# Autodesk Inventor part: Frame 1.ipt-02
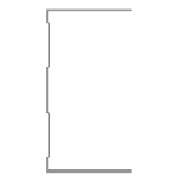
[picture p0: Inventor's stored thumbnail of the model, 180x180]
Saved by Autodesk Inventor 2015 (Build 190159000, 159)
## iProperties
IsCustomPart: 1
Created: 2015-04
Part Number: Frame 1.ipt-02
Material: Aluminum 6061
Description: Kévin Novo
Document SubType Name: Modeling
Standard: Kevin
Designer: suporte
Standards Organization: Kevin
Language: en-US
Size Designation: (Unnamed 2)
Categories: <MemberInstance><Categories><Category DisplayName="Structural Shapes" InternalName="089c4875-fa83-4c05-b084-43b9cc11f5ed" Mnemonic="GRDR"><CategoryParameter Dis
Density: 2.7 g/cm^3
Appearance: Aluminum - Flat
_CCFamilyMember: 2
_CCFamilyDisplayName: Kévin - Kévin Novo
_FrameMemberDoc: Frame Member File
_Version: 15.0.0
_GetPNFromCC: 1
G_W: 50,000 mm
G_H: 75,000 mm
G_L: 742,325 mm
+371032C4-853D-4D1C-9F66-73CC0C0069CB+CUTDETAIL1: Cut
+9BC56BD3-3601-4756-9CD3-DFE412EE9504+CUTDETAIL2: Miter 67,51 deg
Author: suporte
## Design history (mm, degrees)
node "Start Plane"
node "End Plane"
sketch "Sketch"
  geometry: L1 (24.7, 37.5)-(24.7, 36.9); L2 (24.7, 36.9)-(-24.7, 36.9); L3 (-24.7, -36.9)-(24.7, -36.9); L4 (24.7, -36.9)-(24.7, -37.5); L5 (24.7, -37.5)-(-25.3, -37.5); L6 (-25.3, 37.5)-(24.7, 37.5); L7 (-24.7, 36.9)-(-24.7, 31.9); L8 (-24.7, 31.9)-(-23.3, 30.5); L9 (-23.3, 30.5)-(-23.3, 10.934); L10 (-23.3, 10.934)-(-24.7, 9.534); L11 (-24.7, 9.534)-(-24.7, -9.534); L12 (-24.7, -9.534)-(-23.3, -10.934); L13 (-23.3, -10.934)-(-23.3, -30.5); L14 (-23.3, -30.5)-(-24.7, -31.9); L15 (-24.7, -31.9)-(-24.7, -36.9); L16 (-25.3, -37.5)-(-25.3, -31.651); L17 (-25.3, -31.651)-(-23.9, -30.251); L18 (-23.9, -30.251)-(-23.9, -11.183); L19 (-23.9, -11.183)-(-25.3, -9.783); L20 (-25.3, -9.783)-(-25.3, 9.783); L21 (-25.3, 9.783)-(-23.9, 11.183); L22 (-23.9, 11.183)-(-23.9, 30.251); L23 (-23.9, 30.251)-(-25.3, 31.651); L24 (-25.3, 31.651)-(-25.3, 37.5); L25 (-25.3, 0)-(30.37, 0); 3 further points
  constraints: 50 end point, 10 point on line, 9 parallel, 5 perpendicular, 4 equal length, 3 midpoint, 3 vertical, 2 vertical alignment, 1 collinear, 1 horizontal, 1 horizontal alignment
  dimensions: "d3" = 0.6 distance of L1.start L1.end (= d6); "d5" = 75 distance between parallel lines of L5 L6; "d6" = 0.6 distance between parallel lines of L24 L7 (= d8); "d7" = 0.6 distance between parallel lines of L8 L23 (= d8); "d8" = 0.6 distance between parallel lines of L22 L9 (= d12); "Espessura" = 0.6 distance between parallel lines of L17 L14; "d10" = 0.6 distance between parallel lines of L13 L18 (= Espessura); "d11" = 0.6 distance between parallel lines of L12 L19 (= Espessura); "d12" = 0.6 distance between parallel lines of L21 L10 (= d11); "d13" = 5 distance of L2.end L7.end; "d15" = 135 deg angle of L9 L8; "d16" = 2 distance between parallel lines of L24 L9; "d17" = 50 distance of L6.start L1.start
extrude "Body" join sketch "Sketch" stored distance "d24" = 0.13; taper "d25" = 0 deg
node "Driven Length"
  sketch "Sketch10"
    geometry: L1 (0, 0)-(10, 0) reference
    constraints: 2 end point, 1 horizontal
  workplane "Work Plane7"
  sketch "Sketch11"
    geometry: L1 (-2, 12.5)-(12, 12.5) reference; L2 (-2, 754.825)-(12, 754.825) reference
    dimensions: "d27" = 742.32488 distance between parallel lines of L1 L2 (derived)
workplane "Work Plane8"
split "Split1"
workplane "Work Plane9"
split "Split2"
body "Solid1"
other parameters: "tamanho" = 718.59902, "G_OFFSET_START" = -12.5 [user parameter; used in 1 equation term], "G_OFFSET_END" = 36.22585 [user parameter; used in 1 equation term], "d22" = 12.5 (= -G_OFFSET_START), "d23" = 754.82488 (= tamanho + G_OFFSET_END), "G_L" = 742.32488 (= d27) [user parameter], "d34" = 90 deg
